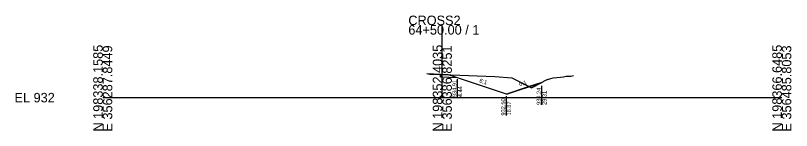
# Model space of a CAD drawing. Extents: x -26 to 203, y -10 to 14021.
# Drawn here: x -25.7 to 202.8, y 5490.3 to 5524.2 of the extents above; entities that cross this region are included whole.
import ezdxf

# ---------------------------------------------------------------- set-up
doc = ezdxf.new("R2010")
doc.units = 0
for name, color, linetype in [('Default', 7, 'Continuous'), ('P_E_XS_Ground', 7, 'Continuous'), ('P_XS', 7, 'Continuous'), ('P_XS_EAR_CommonGrnd', 7, 'Continuous'), ('P_XS_Lane', 7, 'Continuous'), ('P_XS_Rock', 7, 'Continuous')]:
    doc.layers.add(name, color=color, linetype=linetype)

msp = doc.modelspace()

# ---------------------------------------------------------------- linework, layer by layer
at = {"layer": 'Default'}
for p, q in [((100, 5500), (100, 5521.4)), ((0, 5500), (100, 5500)), ((100, 5500), (200, 5500))]:
    msp.add_line(p, q, dxfattribs=at)
at = {"layer": 'P_E_XS_Ground'}
for p, q in [((95.43, 5507.13), (96.35, 5506.97)), ((96.35, 5506.97), (100, 5506.82)), ((100, 5506.82), (115.5, 5506.2)), ((115.5, 5506.2), (120.5, 5505.8)), ((120.5, 5505.8), (126.23, 5502.94)), ((131.01, 5505.33), (131.99, 5505.61)), ((131.99, 5505.61), (132.67, 5505.8)), ((132.67, 5505.8), (134.82, 5506.05)), ((134.82, 5506.05), (135.74, 5506.15)), ((135.74, 5506.15), (136.05, 5506.2)), ((136.05, 5506.2), (136.5, 5506.31)), ((136.5, 5506.31), (137.84, 5506.35)), ((137.84, 5506.35), (138.64, 5506.57)), ((131.01, 5505.33), (126.23, 5502.94))]:
    msp.add_line(p, q, dxfattribs=at)
at = {"layer": 'P_XS'}
for p, q in [((95.43, 5507.13), (99.43, 5506.97)), ((99.43, 5506.97), (101.43, 5506.81)), ((104.44, 5505.81), (101.43, 5506.81))]:
    msp.add_line(p, q, dxfattribs=at)
at = {"layer": 'P_XS_EAR_CommonGrnd'}
for points in [[(115.5, 5506.2), (120.5, 5505.8), (125.61, 5503.25), (118.87, 5501), (104.44, 5505.81), (99.43, 5506.01), (99.43, 5506.84), (100, 5506.82)], [(125.61, 5503.25), (126.23, 5502.94), (129.31, 5504.48)]]:
    msp.add_lwpolyline(points, close=True, dxfattribs=at)
at = {"layer": 'P_XS_Lane'}
for p, q in [((99.43, 5506.84), (99.43, 5506.01)), ((104.44, 5505.81), (99.43, 5506.01)), ((118.87, 5501), (104.44, 5505.81)), ((118.87, 5501), (129.31, 5504.48))]:
    msp.add_line(p, q, dxfattribs=at)
at = {"layer": 'P_XS_Rock'}
for p, q in [((104.39, 5505.46), (104.39, 5500.15)), ((129.24, 5503.45), (129.24, 5497.85)), ((118.79, 5500.43), (118.79, 5494.73))]:
    msp.add_line(p, q, dxfattribs=at)

# ---------------------------------------------------------------- texts
at = {"layer": 'Default'}
for s, p in [('CROSS2', (90, 5521.4)), ('64+50.00 / 1', (90, 5518.6)), ('EL 932', (-26, 5498.6))]:
    msp.add_text(s, height=2.8, dxfattribs=at).set_placement(p)
for s, p in [('N 198338.1585', (0, 5490)), ('E 356287.8449', (2.8, 5490)), ('N 198352.4035', (100, 5490)), ('E 356386.8251', (102.8, 5490)), ('N 198366.6485', (200, 5490)), ('E 356485.8053', (202.8, 5490))]:
    msp.add_text(s, height=2.8, rotation=90, dxfattribs=at).set_placement(p)
at = {"layer": 'P_XS_Rock'}
for s, rotation, p in [('6:1', 341.5651, (110.8, 5504.55)), ('934.91', 90, (104.14, 5500.15)), ('4.44', 90, (105.84, 5500.15)), ('6:1', 18.4349, (122.79, 5503.32)), ('934.24', 90, (128.99, 5497.85)), ('29.31', 90, (130.69, 5497.85)), ('932.50', 90, (118.54, 5494.73)), ('18.87', 90, (120.24, 5494.73))]:
    msp.add_text(s, height=1.2, rotation=rotation, dxfattribs=at).set_placement(p)

doc.saveas('drawing.dxf')
